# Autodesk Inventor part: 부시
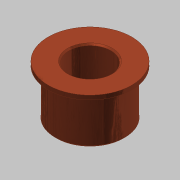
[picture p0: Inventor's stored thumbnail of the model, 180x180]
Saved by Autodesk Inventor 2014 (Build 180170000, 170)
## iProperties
Created: 2015-10
Part Number: 부시
Document SubType Name: Modeling
Designer: mdu
Density: 7.86 g/cm^3
Material: 강철, 연강
Mass: 374.583 g
Surface Area: 131.821 cm^2
Volume: 47.6569 cm^3
Appearance: Copper - Satin
Author: mdu
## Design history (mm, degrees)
sketch "스케치1"
  geometry: C1 r 31 at (0, 0) reference; C2 r 25 at (0, 0) reference; C3 r 30 at (0, 0) reference; 1 further point
  node "참조1"
  node "참조2"
  node "참조4"
extrude "돌출1" new body sketch "스케치1" distance "d0" = 3; taper "d1" = 0 deg
extrude "돌출2" join sketch "스케치1" distance "d2" = 36; taper "d3" = 0 deg
chamfer "모따기1" distance "d6" = 1; stored, may be unused: second distance "d7" = 2, angle "d8" = 45 deg
sketch "스케치3"
  geometry: C1 r 15 at (0, 0); 1 further point
  constraints: 1 centre point, 1 coincident
  dimensions: "d13" = 30 diameter of C1
extrude "돌출4" cut sketch "스케치3" stored distance "d14" = 10; taper "d15" = 0 deg
chamfer "모따기3" distance "d16" = 1; stored, may be unused: second distance "d17" = 2, angle "d18" = 45 deg
node "솔리드1"
